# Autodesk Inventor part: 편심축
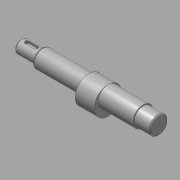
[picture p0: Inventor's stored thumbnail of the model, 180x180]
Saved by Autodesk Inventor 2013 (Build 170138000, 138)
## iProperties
Created: 2017-08
Part Number: 편심축
Material: 강철, 연강
Document SubType Name: Modeling
Designer: mduedu
Density: 1 g/cm^3
Author: mduedu
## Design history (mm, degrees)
sketch "스케치1"
  geometry: L1 (0, 0)-(150, 0); L2 (150, 0)-(150, 8.5); L3 (150, 8.5)-(135, 8.5); L4 (135, 8.5)-(135, 9.5); L5 (135, 9.5)-(51, 9.5); L6 (51, 9.5)-(51, 8.5); L7 (51, 8.5)-(19, 8.5); L8 (19, 8.5)-(19, 6); L9 (19, 6)-(0, 6); L10 (0, 6)-(0, 0)
  constraints: 20 end point, 6 parallel, 2 collinear, 2 perpendicular, 1 horizontal
  dimensions: "d0" = 150 distance of L1.start L1.end; "d1" = 17 diameter of L3 L1; "d2" = 19 diameter of L5 L1; "d3" = 12 diameter of L9 L1; "d4" = 19 distance of L8.end L9.end; "d5" = 15 distance of L2.end L3.end; "d6" = 84 distance of L4.end L5.end
revolve "회전1" sketch "스케치1" stored, may be unused: angle "d7" = 90 deg
node "작업 평면1"
sketch "스케치2"
  geometry: C1 r 9.5 at (0, 0) reference; C2 r 13 at (0, -3.5); 1 further point
  constraints: 1 centre point, 1 tangent, 1 vertical alignment
  dimensions: "d8" = 3.5 distance of point (0, 0) C2.centre
extrude "돌출1" join sketch "스케치2" stored distance "d9" = 18; taper "d10" = 0 deg
chamfer "모따기1" distance "d11" = 1; stored, may be unused: second distance "d12" = 2, angle "d13" = 45 deg
node "작업 평면2"
sketch "스케치3"
  geometry: L1 (3.5, -2)-(-4.5, -2); L2 (-4.5, -2)-(-4.5, 2); L3 (-4.5, 2)-(3.5, 2); L4 (3.5, 2)-(3.5, -2); L5 (9.5, 6)-(9.5, -6) reference; A1 r 2 centre (3.5, 0) between (3.5, -2) and (3.5, 2); A2 r 2 centre (-4.5, 0) between (-4.5, 2) and (-4.5, -2); A3 r 2 centre (3.5, 0) between (3.5, 2) and (3.5, -2); A4 r 2 centre (-4.5, 0) between (-4.5, -2) and (-4.5, 2); 1 further point
  constraints: 8 end point, 8 point on circle, 4 centre point, 2 midpoint, 2 parallel, 1 horizontal, 1 horizontal alignment, 1 perpendicular
  dimensions: "d14" = 12 dimension on A2 A1; "d16" = 4 distance between parallel lines of L3 L1; "d17" = 4 distance edge to line of A1 L5
extrude "돌출2" cut sketch "스케치3" distance "d18" = 2.5; taper "d19" = 0 deg
chamfer "모따기2" distance "d20" = 1; stored, may be unused: second distance "d21" = 2, angle "d22" = 45 deg
chamfer "모따기3" distance "d23" = 1; stored, may be unused: second distance "d24" = 2, angle "d25" = 60 deg
fillet "모깎기1" dims "d26" = 0.5
hole "구멍1" diameter "d29" = 3.242; stored, may be unused: countersink angle "d33" = 90 deg, drill point angle "d35" = 118 deg; dims "d30" = 8, "d31" = 4, "d32" = 2, "d34" = 10, "d36" = 10, "d37" = 10
node "솔리드1"
node "절단 모서리 투영1"
other parameters: "d38" = -42
